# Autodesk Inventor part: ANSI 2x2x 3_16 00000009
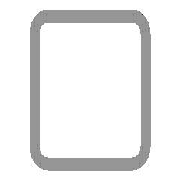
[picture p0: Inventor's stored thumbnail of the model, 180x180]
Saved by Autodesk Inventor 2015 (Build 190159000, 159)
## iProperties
IsCustomPart: 1
Created: 2007-02
Part Number: ANSI 2x2x 3_16 00000009
Material: Steel
Document SubType Name: Modeling
Standard: AISC
Designer: Autodesk, Inc.
Size Designation: 2x2x3/16
Stock Number: 2x2x 3/16
Density: 7.85 g/cm^3
Description: Tube
Standards Organization: ANSI
Language: en-US
Categories: <MemberInstance><Categories><Category DisplayName="Structural Shapes" InternalName="089c4875-fa83-4c05-b084-43b9cc11f5ed" Mnemonic="GRDR"><CategoryParameter Dis
Mass: 4523.85 g
Surface Area: 2436.47 cm^2
Volume: 576.287 cm^3
Appearance: Steel
_FrameMemberDoc: Frame Member File
_Version: 15.0.0
_CCFamilyMember: 1
_CCFamilyDisplayName: ANSI AISC (Square) - Tube
G_L: 27.716 in
G_W: 2.000 in
G_H: 2.000 in
+BFFA720C-4E85-427B-A7D8-FC9756C096E1+CUTDETAIL1: Cut
Author: Autodesk, Inc.
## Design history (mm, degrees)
node "Start plane"
node "End plane"
sketch "Sketch"
  geometry: L1 (-25.4, -15.875)-(-25.4, 15.875); L2 (-15.875, 25.4)-(15.875, 25.4); L3 (25.4, 15.875)-(25.4, -15.875); L4 (15.875, -25.4)-(-15.875, -25.4); L5 (-15.875, 20.637)-(15.875, 20.638); L6 (20.637, 15.875)-(20.637, -15.875); L7 (15.875, -20.637)-(-15.875, -20.638); L8 (-20.637, -15.875)-(-20.637, 15.875); L9 (0, 38.322)-(0, -38.322) reference; L10 (-38.322, 0)-(38.322, 0) reference; A1 r 9.525 centre (-15.875, -15.875) between (-25.4, -15.875) and (-15.875, -25.4); A2 r 9.525 centre (-15.875, 15.875) between (-15.875, 25.4) and (-25.4, 15.875); A3 r 9.525 centre (15.875, 15.875) between (25.4, 15.875) and (15.875, 25.4); A4 r 9.525 centre (15.875, -15.875) between (15.875, -25.4) and (25.4, -15.875); A5 r 4.762 centre (-15.875, 15.875) between (-15.875, 20.637) and (-20.637, 15.875); A6 r 4.762 centre (15.875, 15.875) between (20.637, 15.875) and (15.875, 20.638); A7 r 4.762 centre (15.875, -15.875) between (15.875, -20.637) and (20.637, -15.875); A8 r 4.762 centre (-15.875, -15.875) between (-20.637, -15.875) and (-15.875, -20.638)
  constraints: 16 end point, 16 point on circle, 8 centre point, 8 tangent, 4 parallel, 3 equal radius, 2 perpendicular, 7 other
  dimensions: "d10" = 50.8 distance between parallel lines of L2 L4 (= G_H); "d11" = 50.8 distance between parallel lines of L1 L3 (= G_W); "d12" = 4.7625 distance between parallel lines of L3 L6 (= G_T); "d15" = 25.4 distance between parallel lines of L2 L10 (= 0.5 x d10); "d16" = 25.4 distance between parallel lines of L9 L3 (= 0.5 x d11); "d17" = 9.525 radius of A1 (= G_IR)
extrude "Body" new body sketch "Sketch" stored distance "d3" = 703.9864 (= G_L); taper "d4" = 0 deg
node "Driven Length"
  sketch "Sketch3"
    geometry: L1 (0, 0)-(10, 0) reference
    constraints: 2 end point, 1 horizontal
  workplane "Work Plane4"
  sketch "Sketch4"
    geometry: L1 (-2, 0)-(12, 0) reference; L2 (-2, 703.986)-(12, 703.986) reference
    dimensions: "d19" = 703.9864 distance between parallel lines of L1 L2 (derived)
workplane "Work Plane3"
split "Split1"
body "Solid1"
other parameters: "G_W" = 50.8 [user parameter; used in 1 equation term], "G_H" = 50.8 [user parameter; used in 1 equation term], "G_T" = 4.7625 [user parameter; used in 1 equation term], "G_IR" = 9.525 [user parameter; used in 1 equation term], "G_L" = 703.9864 (= d19) [user parameter; used in 1 equation term], "G_OFFSET_START" = 0 [user parameter; used in 1 equation term], "G_OFFSET_END" = -50.8 [user parameter; used in 1 equation term], "d13" = 0 (computed from G_OFFSET_START), "d14" = 703.9864 (= G_OFFSET_END + B_L), "B_L" = 754.7864 [user parameter; used in 1 equation term], "d18" = 90 deg
